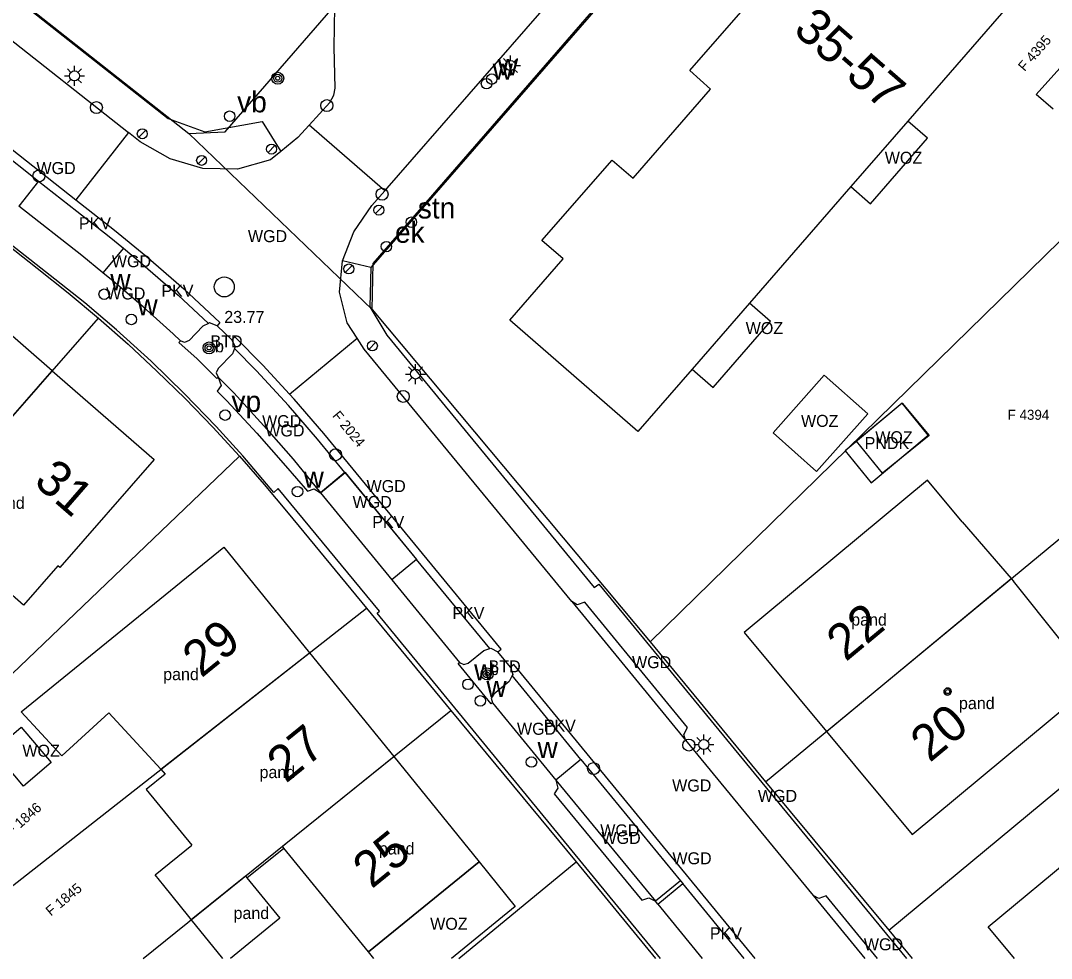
# Model space of a CAD drawing. Extents: x 198240 to 198429, y 356553 to 356721.
# Drawn here: x 198326.7 to 198378.2, y 356553.7 to 356600.6 of the extents above; entities that cross this region are included whole.
import ezdxf

# ---------------------------------------------------------------- set-up
doc = ezdxf.new("R2010")
doc.units = 0
for name, color, linetype in [('(presentatie) Code PNDK (symbool) (zonder attributen) niet in de presentatietabel', 7, 'Continuous'), ('Afsluitpaal', 7, 'Continuous'), ('begroeid terreindeel kenmerkpunt', 7, 'Continuous'), ('Benzineput_olieput', 7, 'Continuous'), ('bijgebouw', 7, 'Continuous'), ('BOOM', 7, 'Continuous'), ('Elektrakast', 7, 'Continuous'), ('grens individueel parkeervak', 7, 'Continuous'), ('Grens maaiveld', 7, 'Continuous'), ('grens WOZ object', 7, 'Continuous'), ('hoofdgebouw', 7, 'Continuous'), ('Hoogtepunt', 7, 'Continuous'), ('huisnummerreeks BGT', 7, 'Continuous'), ('identificerend kenmerkpunt bijpand', 7, 'Continuous'), ('identificerend kenmerkpunt pand', 7, 'Continuous'), ('identificerend kenmerkpunt parkeervak', 7, 'Continuous'), ('identificerend kenmerkpunt WOZ object', 7, 'Continuous'), ('Inspectieput_rioolput', 7, 'Continuous'), ('kant verharding', 7, 'Continuous'), ('kolk', 7, 'Continuous'), ('LICHTMAST', 7, 'Continuous'), ('Perceelnummer', 7, 'Continuous'), ('perceelsgrens_definitief', 7, 'Continuous'), ('straatnaambord', 7, 'Continuous'), ('tussenmuur', 7, 'Continuous'), ('Verkeersbordpaal', 7, 'Continuous'), ('vlakafsluiter', 7, 'Continuous'), ('waterleidingput', 7, 'Continuous'), ('wegdeel kenmerkpunt', 7, 'Continuous'), ('weginrichtingselement', 7, 'Continuous'), ('weginrichtingselement lijn', 7, 'Continuous'), ('WOZ object als punt', 7, 'Continuous')]:
    doc.layers.add(name, color=color, linetype=linetype)

msp = doc.modelspace()

# ---------------------------------------------------------------- linework, layer by layer
at = {"layer": 'Afsluitpaal'}
for p, q in [((198332.936, 356595.135), (198332.586, 356594.778)), ((198339.402, 356594.368), (198339.052, 356594.011)), ((198335.905, 356593.805), (198335.555, 356593.448)), ((198344.772, 356591.316), (198344.422, 356590.959)), ((198343.267, 356588.372), (198342.917, 356588.015)), ((198344.446, 356584.522), (198344.096, 356584.165))]:
    msp.add_line(p, q, dxfattribs=at)
for centre in [(198332.763, 356594.955), (198339.229, 356594.188), (198335.732, 356593.625), (198344.599, 356591.136), (198343.094, 356588.192), (198344.273, 356584.342)]:
    msp.add_circle(centre, 0.25, dxfattribs=at)
at = {"layer": 'Benzineput_olieput'}
msp.add_circle((198336.905, 356580.881), 0.263, dxfattribs=at)
msp.add_circle((198336.905, 356580.881), 0.263, dxfattribs=at)
at = {"layer": 'bijgebouw'}
for points in [[(198338.001, 356557.734), (198339.644, 356555.708), (198337.168, 356553.702)], [(198336.789, 356553.702), (198335.216, 356555.641)]]:
    msp.add_lwpolyline(points, dxfattribs=at)
at = {"layer": 'BOOM'}
for centre, radius in [((198339.538, 356597.733), 0.3), ((198339.538, 356597.733), 0.2), ((198339.538, 356597.733), 0.1), ((198336.101, 356584.239), 0.3), ((198336.101, 356584.239), 0.2), ((198336.101, 356584.239), 0.1), ((198350.016, 356567.934), 0.3), ((198350.016, 356567.934), 0.2), ((198350.016, 356567.934), 0.1)]:
    msp.add_circle(centre, radius, dxfattribs=at)
at = {"layer": 'Elektrakast'}
msp.add_circle((198344.975, 356589.31), 0.263, dxfattribs=at)
msp.add_circle((198344.975, 356589.31), 0.263, dxfattribs=at)
at = {"layer": 'grens individueel parkeervak'}
for p, q in [((198327.572, 356592.592), (198326.591, 356591.338)), ((198331.82, 356589.23), (198330.793, 356588.001)), ((198342.903, 356578.007), (198341.674, 356576.997)), ((198342.903, 356578.007), (198346.485, 356573.651)), ((198346.485, 356573.651), (198345.25, 356572.636)), ((198354.71, 356563.653), (198353.457, 356562.625)), ((198358.553, 356556.415), (198359.805, 356557.441))]:
    msp.add_line(p, q, dxfattribs=at)
at = {"layer": 'Grens maaiveld'}
for p, q in [((198332.081, 356595.014), (198329.434, 356591.655)), ((198344.897, 356592.108), (198341.11, 356595.383)), ((198340.134, 356581.92), (198343.518, 356584.725)), ((198341.674, 356576.997), (198342.904, 356578.006)), ((198342.904, 356578.006), (198342.903, 356578.007)), ((198342.904, 356578.006), (198346.485, 356573.651)), ((198354.71, 356563.653), (198359.687, 356557.585)), ((198359.687, 356557.585), (198358.436, 356556.558)), ((198359.687, 356557.585), (198359.805, 356557.441))]:
    msp.add_line(p, q, dxfattribs=at)
for points in [[(198311.777, 356613.258), (198312.501, 356612.688), (198316.479, 356609.557), (198334.051, 356595.726), (198335.895, 356595.044), (198338.762, 356595.561)], [(198318.292, 356600.168), (198318.429, 356600.335), (198329.434, 356591.655)], [(198329.434, 356591.655), (198331.374, 356590.125), (198332.937, 356588.842), (198334.833, 356587.192), (198336.644, 356585.51), (198336.504, 356585.346)], [(198328.26, 356583.099), (198323.101, 356587.58), (198317.022, 356580.581)], [(198337.248, 356584.646), (198337.387, 356584.794), (198338.788, 356583.375), (198340.134, 356581.92)], [(198350.553, 356569.041), (198350.715, 356569.174), (198341.85, 356579.957), (198340.363, 356581.672), (198340.134, 356581.92)], [(198370.778, 356581.471), (198367.918, 356579.09), (198369.226, 356577.489), (198372.086, 356579.869), (198370.778, 356581.471)], [(198363.416, 356553.702), (198351.352, 356568.4), (198351.188, 356568.267)]]:
    msp.add_lwpolyline(points, dxfattribs=at)
at = {"layer": 'grens WOZ object'}
for p, q in [((198370.778, 356581.471), (198368.494, 356579.573)), ((198370.778, 356581.471), (198372.121, 356579.855)), ((198369.788, 356577.971), (198368.494, 356579.573)), ((198372.121, 356579.855), (198369.788, 356577.971)), ((198325.32, 356564.087), (198326.702, 356565.264)), ((198326.702, 356565.264), (198328.21, 356563.494)), ((198326.828, 356562.317), (198325.32, 356564.087)), ((198328.21, 356563.494), (198326.828, 356562.317)), ((198344.074, 356554.032), (198349.616, 356558.527)), ((198349.616, 356558.527), (198351.423, 356556.299)), ((198351.423, 356556.299), (198348.226, 356553.702)), ((198344.342, 356553.702), (198344.074, 356554.032))]:
    msp.add_line(p, q, dxfattribs=at)
for points in [[(198378.332, 356596.184), (198377.486, 356596.927), (198380.014, 356599.745), (198380.819, 356599.057)], [(198368.212, 356592.309), (198369.191, 356591.458), (198372.045, 356594.74), (198371.066, 356595.591)], [(198360.274, 356583.182), (198361.325, 356582.267), (198364.189, 356585.561), (198363.138, 356586.475)], [(198364.316, 356579.994), (198366.882, 356582.876), (198369.06, 356580.937), (198366.494, 356578.055), (198364.316, 356579.994)]]:
    msp.add_lwpolyline(points, dxfattribs=at)
at = {"layer": 'hoofdgebouw'}
for p, q in [((198376.42, 356601.748), (198371.066, 356595.591)), ((198371.066, 356595.591), (198368.212, 356592.309)), ((198368.212, 356592.309), (198363.138, 356586.475)), ((198363.138, 356586.475), (198360.274, 356583.182)), ((198373.784, 356575.541), (198376.235, 356572.701)), ((198376.235, 356572.701), (198376.341, 356572.579)), ((198378.73, 356569.587), (198376.341, 356572.579)), ((198341.127, 356568.99), (198345.342, 356563.794)), ((198338.001, 356557.734), (198339.848, 356559.221)), ((198335.084, 356555.804), (198333.833, 356557.347)), ((198335.216, 356555.641), (198335.084, 356555.804))]:
    msp.add_line(p, q, dxfattribs=at)
for points in [[(198360.274, 356583.182), (198357.56, 356580.061), (198351.153, 356585.634), (198353.818, 356588.702), (198352.758, 356589.611), (198356.269, 356593.637), (198357.324, 356592.737), (198361.192, 356597.186), (198360.148, 356598.119), (198363.635, 356602.123), (198364.703, 356601.223), (198369.86, 356607.147), (198368.781, 356608.057), (198372.281, 356612.093), (198373.369, 356611.185), (198377.239, 356615.604), (198376.168, 356616.531), (198379.668, 356620.576), (198380.75, 356619.653), (198383.405, 356622.721), (198387.106, 356619.502)], [(198328.26, 356583.099), (198333.365, 356578.665), (198328.634, 356573.26), (198328.544, 356573.339), (198326.816, 356571.37), (198323.857, 356573.967), (198321.738, 356571.528)], [(198373.784, 356575.541), (198372.046, 356577.633), (198362.87, 356570.009), (198366.989, 356565.052)], [(198328.73, 356563.83), (198326.698, 356566.044), (198336.841, 356574.272), (198341.127, 356568.99)], [(198366.989, 356565.052), (198371.275, 356559.894), (198380.45, 356567.516), (198378.73, 356569.587)], [(198328.73, 356563.83), (198331.088, 356565.993), (198333.686, 356563.16)], [(198345.342, 356563.794), (198349.616, 356558.527), (198344.074, 356554.032), (198339.848, 356559.221)], [(198333.686, 356563.16), (198333.902, 356562.925), (198332.951, 356562.145), (198335.236, 356559.358)], [(198376.395, 356553.702), (198375.087, 356555.277), (198384.259, 356562.891), (198385.996, 356560.798)], [(198333.833, 356557.347), (198333.406, 356557.874), (198335.236, 356559.358)]]:
    msp.add_lwpolyline(points, dxfattribs=at)
at = {"layer": 'Inspectieput_rioolput'}
msp.add_circle((198336.865, 356587.293), 0.5, dxfattribs=at)
at = {"layer": 'kant verharding'}
for p, q in [((198288.208, 356629.517), (198332.081, 356595.014)), ((198344.897, 356592.108), (198377.168, 356629.077)), ((198322.687, 356596.444), (198327.572, 356592.592)), ((198338.762, 356595.561), (198339.693, 356594.074)), ((198336.504, 356585.346), (198337.248, 356584.646)), ((198341.674, 356576.997), (198345.25, 356572.636)), ((198350.146, 356569.199), (198346.485, 356573.651)), ((198345.25, 356572.636), (198348.633, 356568.509)), ((198354.249, 356571.548), (198359.938, 356564.624)), ((198351.188, 356568.267), (198350.553, 356569.041)), ((198354.71, 356563.653), (198351.264, 356567.853)), ((198350.285, 356566.492), (198353.457, 356562.625)), ((198359.938, 356564.624), (198366.321, 356556.854)), ((198353.457, 356562.625), (198358.436, 356556.558)), ((198362.873, 356553.702), (198359.805, 356557.441)), ((198366.321, 356556.854), (198368.91, 356553.702)), ((198358.553, 356556.415), (198358.436, 356556.558)), ((198358.553, 356556.415), (198360.779, 356553.702))]:
    msp.add_line(p, q, dxfattribs=at)
for points in [[(198382.054, 356630.413), (198380.73, 356630.231), (198344.191, 356588.273)], [(198358.681, 356553.702), (198344.512, 356570.974), (198344.626, 356571.073), (198339.557, 356577.216), (198339.341, 356577.012), (198337.792, 356578.849), (198336.463, 356580.312), (198334.882, 356581.942), (198333.211, 356583.577), (198331.471, 356585.153), (198329.894, 356586.497), (198328.385, 356587.677), (198287.334, 356619.961)], [(198341.11, 356595.383), (198342.151, 356596.522), (198342.345, 356596.889), (198342.404, 356597.244), (198342.367, 356599.296), (198342.392, 356601.284), (198342.457, 356602.444)], [(198339.693, 356594.074), (198339.175, 356593.653), (198337.534, 356593.192), (198335.794, 356593.217), (198334.158, 356593.695), (198332.658, 356594.56), (198332.081, 356595.014)], [(198341.11, 356595.383), (198340.545, 356594.766), (198339.693, 356594.074)], [(198327.572, 356592.592), (198329.494, 356591.076), (198331.112, 356589.821), (198331.82, 356589.23)], [(198342.782, 356588.597), (198343.346, 356590.05), (198344.246, 356591.363), (198344.897, 356592.108)], [(198330.793, 356588.001), (198329.743, 356588.86), (198326.591, 356591.338)], [(198331.82, 356589.23), (198332.654, 356588.534), (198334.555, 356586.882), (198336.07, 356585.465)], [(198343.518, 356584.725), (198343.015, 356585.5), (198342.628, 356587.025), (198342.782, 356588.597)], [(198344.191, 356588.273), (198344.153, 356586.301), (198344.997, 356584.886), (198355.366, 356572.263), (198355.605, 356572.429), (198370.986, 356553.702)], [(198334.673, 356584.594), (198334.309, 356584.941), (198332.811, 356586.291), (198331.299, 356587.587), (198330.793, 356588.001)], [(198336.07, 356585.465), (198335.798, 356585.333), (198335.102, 356584.613), (198334.875, 356584.519), (198334.673, 356584.594)], [(198336.504, 356585.346), (198336.131, 356585.494), (198336.07, 356585.465)], [(198334.673, 356584.594), (198334.595, 356584.511), (198335.503, 356583.692), (198336.487, 356582.704), (198336.558, 356582.783)], [(198337.248, 356584.646), (198337.409, 356584.298), (198337.377, 356584.216)], [(198354.249, 356571.548), (198343.87, 356584.183), (198343.518, 356584.725)], [(198337.377, 356584.216), (198337.268, 356583.938), (198336.561, 356583.213), (198336.454, 356582.999), (198336.558, 356582.783)], [(198342.903, 356578.007), (198341.535, 356579.671), (198340.073, 356581.357), (198338.472, 356583.095), (198337.377, 356584.216)], [(198336.558, 356582.783), (198336.709, 356582.357), (198336.514, 356582.079), (198336.994, 356581.587), (198338.49, 356579.97), (198339.928, 356578.339), (198341.021, 356577.07), (198341.36, 356577.184), (198341.674, 356576.997)], [(198336.558, 356582.783), (198337.341, 356582.003), (198338.844, 356580.339), (198340.303, 356578.669), (198341.674, 356576.997)], [(198359.938, 356564.624), (198359.85, 356564.909), (198360.046, 356565.251), (198354.903, 356571.519), (198354.512, 356571.388), (198354.249, 356571.548)], [(198348.633, 356568.509), (198348.855, 356568.397), (198349.071, 356568.476), (198349.842, 356569.1), (198350.146, 356569.199)], [(198350.146, 356569.199), (198350.203, 356569.218), (198350.553, 356569.041)], [(198350.285, 356566.492), (198350.213, 356566.432), (198348.567, 356568.459), (198348.633, 356568.509)], [(198351.188, 356568.267), (198351.293, 356567.909), (198351.264, 356567.853)], [(198351.264, 356567.853), (198351.11, 356567.551), (198350.342, 356566.925), (198350.218, 356566.724), (198350.285, 356566.492)], [(198353.457, 356562.625), (198353.552, 356562.215), (198353.365, 356561.931), (198357.748, 356556.607), (198358.099, 356556.731), (198358.436, 356556.558)], [(198369.541, 356553.702), (198366.969, 356556.825), (198366.6, 356556.701), (198366.321, 356556.854)]]:
    msp.add_lwpolyline(points, dxfattribs=at)
at = {"layer": 'kolk'}
for centre in [(198330.468, 356596.267), (198341.996, 356596.364), (198327.59, 356592.846), (198344.757, 356591.932), (198345.818, 356581.813), (198342.433, 356578.901), (198360.106, 356564.374), (198355.338, 356563.198)]:
    msp.add_circle(centre, 0.3, dxfattribs=at)
at = {"layer": 'LICHTMAST'}
for p, q in [((198351.002, 356598.545), (198350.825, 356598.722)), ((198351.179, 356598.618), (198351.179, 356598.868)), ((198351.356, 356598.545), (198351.533, 356598.722)), ((198329.191, 356598.028), (198329.014, 356598.205)), ((198329.368, 356598.101), (198329.368, 356598.351)), ((198329.545, 356598.028), (198329.722, 356598.205)), ((198350.679, 356598.368), (198350.929, 356598.368)), ((198350.825, 356598.014), (198351.002, 356598.191)), ((198351.179, 356597.868), (198351.179, 356598.118)), ((198351.533, 356598.014), (198351.356, 356598.191)), ((198351.429, 356598.368), (198351.679, 356598.368)), ((198328.868, 356597.851), (198329.118, 356597.851)), ((198329.014, 356597.497), (198329.191, 356597.674)), ((198329.368, 356597.351), (198329.368, 356597.601)), ((198329.722, 356597.497), (198329.545, 356597.674)), ((198329.618, 356597.851), (198329.868, 356597.851)), ((198346.256, 356583.112), (198346.079, 356583.289)), ((198346.433, 356583.185), (198346.433, 356583.435)), ((198346.61, 356583.112), (198346.787, 356583.289)), ((198345.933, 356582.935), (198346.183, 356582.935)), ((198346.079, 356582.581), (198346.256, 356582.758)), ((198346.433, 356582.435), (198346.433, 356582.685)), ((198346.787, 356582.581), (198346.61, 356582.758)), ((198346.683, 356582.935), (198346.933, 356582.935)), ((198360.682, 356564.574), (198360.505, 356564.751)), ((198360.859, 356564.647), (198360.859, 356564.897)), ((198361.036, 356564.574), (198361.213, 356564.751)), ((198360.359, 356564.397), (198360.609, 356564.397)), ((198360.505, 356564.043), (198360.682, 356564.22)), ((198360.859, 356563.897), (198360.859, 356564.147)), ((198361.213, 356564.043), (198361.036, 356564.22)), ((198361.109, 356564.397), (198361.359, 356564.397))]:
    msp.add_line(p, q, dxfattribs=at)
for centre in [(198351.179, 356598.368), (198329.368, 356597.851), (198346.433, 356582.935), (198360.859, 356564.397)]:
    msp.add_circle(centre, 0.25, dxfattribs=at)
at = {"layer": 'perceelsgrens_definitief'}
for points in [[(198335.086, 356594.965), (198336.909, 356595.05), (198372.498, 356636.045)], [(198287.646, 356632.339), (198335.086, 356594.965)], [(198344.27, 356586.164), (198344.308, 356588.473), (198380.117, 356629.684), (198382.048, 356630.256)], [(198335.086, 356594.965), (198344.27, 356586.164)], [(198322.937, 356591.83), (198327.497, 356588.229)], [(198358.164, 356569.531), (198380.205, 356591.088)], [(198327.497, 356588.229), (198329.048, 356587.003), (198330.567, 356585.738)], [(198344.27, 356586.164), (198358.164, 356569.531)], [(198312.565, 356565.146), (198330.567, 356585.738)], [(198330.567, 356585.738), (198332.05, 356584.431), (198333.498, 356583.086), (198334.91, 356581.703), (198336.285, 356580.284), (198337.623, 356578.829)], [(198363.947, 356562.536), (198387.979, 356582.417)], [(198317.612, 356559.68), (198337.623, 356578.829)], [(198337.623, 356578.829), (198338.855, 356577.413), (198340.054, 356575.969)], [(198370.106, 356555.109), (198394.44, 356575.297), (198393.504, 356576.321)], [(198340.054, 356575.969), (198343.976, 356571.222)], [(198322.461, 356554.365), (198343.976, 356571.222)], [(198343.976, 356571.222), (198348.206, 356566.1)], [(198358.164, 356569.531), (198363.947, 356562.536)], [(198332.808, 356553.702), (198348.206, 356566.1)], [(198348.206, 356566.1), (198354.461, 356558.524)], [(198363.947, 356562.536), (198370.106, 356555.109)], [(198348.592, 356553.702), (198354.461, 356558.524)], [(198354.461, 356558.524), (198358.444, 356553.702)], [(198370.106, 356555.109), (198371.272, 356553.702)]]:
    msp.add_lwpolyline(points, dxfattribs=at)
at = {"layer": 'straatnaambord'}
msp.add_circle((198346.224, 356590.532), 0.263, dxfattribs=at)
msp.add_circle((198346.224, 356590.532), 0.263, dxfattribs=at)
at = {"layer": 'tussenmuur'}
for p, q in [((198322.202, 356576.169), (198328.26, 356583.099)), ((198366.989, 356565.052), (198376.235, 356572.701)), ((198333.686, 356563.16), (198341.127, 356568.99))]:
    msp.add_line(p, q, dxfattribs=at)
for points in [[(198339.848, 356559.221), (198339.774, 356559.311), (198345.342, 356563.794)], [(198335.216, 356555.641), (198337.928, 356557.824), (198338.001, 356557.734)]]:
    msp.add_lwpolyline(points, dxfattribs=at)
at = {"layer": 'Verkeersbordpaal'}
msp.add_circle((198337.134, 356595.834), 0.263, dxfattribs=at)
at = {"layer": 'vlakafsluiter'}
msp.add_line((198344.191, 356588.273), (198342.782, 356588.597), dxfattribs=at)
at = {"layer": 'waterleidingput'}
for centre in [(198349.987, 356597.462), (198349.987, 356597.462), (198350.244, 356597.688), (198350.244, 356597.688), (198330.859, 356586.928), (198330.859, 356586.928), (198332.215, 356585.667), (198332.215, 356585.667), (198340.528, 356577.054), (198340.528, 356577.054), (198349.058, 356567.411), (198349.058, 356567.411), (198349.672, 356566.582), (198349.672, 356566.582), (198352.232, 356563.523), (198352.232, 356563.523)]:
    msp.add_circle(centre, 0.263, dxfattribs=at)
at = {"layer": 'weginrichtingselement lijn'}
for points in [[(198318.292, 356600.168), (198318.429, 356600.335), (198329.434, 356591.655)], [(198329.434, 356591.655), (198331.374, 356590.125), (198332.937, 356588.842), (198334.833, 356587.192), (198336.644, 356585.51), (198336.504, 356585.346)], [(198337.248, 356584.646), (198337.387, 356584.794), (198338.788, 356583.375), (198340.134, 356581.92)], [(198350.553, 356569.041), (198350.715, 356569.174), (198341.85, 356579.957), (198340.363, 356581.672), (198340.134, 356581.92)], [(198363.416, 356553.702), (198351.352, 356568.4), (198351.188, 356568.267)]]:
    msp.add_lwpolyline(points, dxfattribs=at)
at = {"layer": 'WOZ object als punt'}
for radius in [0.178, 0.178, 0.178, 0.178, 0.1, 0.1, 0.1, 0.1]:
    msp.add_circle((198373.05, 356567.048), radius, dxfattribs=at)
for start, end in [(0, 180), (0, 180), (0, 180), (0, 180), (0, 180), (0, 180), (0, 180), (0, 180), (180, 0), (180, 0), (180, 0), (180, 0), (180, 0), (180, 0), (180, 0), (180, 0)]:
    msp.add_arc((198373.05, 356567.048), 0.178, start, end, dxfattribs=at)

# ---------------------------------------------------------------- texts
at = {"layer": '(presentatie) Code PNDK (symbool) (zonder attributen) niet in de presentatietabel'}
msp.add_text('PNDK', height=0.6, dxfattribs=at).set_placement((198368.901, 356579.18))
at = {"layer": 'begroeid terreindeel kenmerkpunt'}
for p in [(198336.176, 356584.27), (198350.088, 356568.01)]:
    msp.add_text('BTD', height=0.6, dxfattribs=at).set_placement(p)
at = {"layer": 'Benzineput_olieput'}
msp.add_text('vp', height=1.05, dxfattribs=at).set_placement((198337.225, 356581.042))
at = {"layer": 'Elektrakast'}
msp.add_text('ek', height=1.05, dxfattribs=at).set_placement((198345.404, 356589.501))
at = {"layer": 'Hoogtepunt'}
msp.add_text('23.77', height=0.6, dxfattribs=at).set_placement((198336.865, 356585.493))
msp.add_text('23.77', height=0.6, dxfattribs=at).set_placement((198336.865, 356585.493))
at = {"layer": 'huisnummerreeks BGT'}
for s, rotation, p in [('35-57', 319, (198365.268, 356600.059)), ('31', 319, (198327.272, 356577.467)), ('22', 39.7, (198367.956, 356568.513)), ('29', 39.1, (198335.718, 356567.7)), ('20', 39.7, (198372.155, 356563.468)), ('27', 39, (198339.946, 356562.431)), ('25', 39.1, (198344.24, 356557.15))]:
    msp.add_text(s, height=1.8, rotation=rotation, dxfattribs=at).set_placement(p)
at = {"layer": 'identificerend kenmerkpunt bijpand'}
msp.add_text('pand', height=0.6, dxfattribs=at).set_placement((198337.328, 356555.67))
at = {"layer": 'identificerend kenmerkpunt pand'}
for p in [(198325.098, 356576.19), (198368.228, 356570.35), (198333.808, 356567.62), (198373.618, 356566.17), (198338.628, 356562.72), (198344.598, 356558.9)]:
    msp.add_text('pand', height=0.6, dxfattribs=at).set_placement(p)
at = {"layer": 'identificerend kenmerkpunt parkeervak'}
for p in [(198329.595, 356590.182), (198333.718, 356586.8), (198344.265, 356575.239), (198348.277, 356570.685), (198352.846, 356565.049), (198361.157, 356554.654)]:
    msp.add_text('PKV', height=0.6, dxfattribs=at).set_placement(p)
at = {"layer": 'identificerend kenmerkpunt WOZ object'}
for p in [(198369.907, 356593.454), (198362.95, 356584.935), (198365.717, 356580.293), (198369.432, 356579.474), (198326.765, 356563.791), (198347.165, 356555.131)]:
    msp.add_text('WOZ', height=0.6, dxfattribs=at).set_placement(p)
at = {"layer": 'Perceelnummer'}
for s, rotation, p in [('F 4395', 49.1, (198376.907, 356598.041)), ('F 2024', 309.6, (198342.242, 356580.835)), ('F 1846', 41.4, (198326.208, 356559.795)), ('F 1845', 39.7, (198328.19, 356555.794))]:
    msp.add_text(s, height=0.5, rotation=rotation, dxfattribs=at).set_placement(p)
msp.add_text('F 4394', height=0.5, dxfattribs=at).set_placement((198376.055, 356580.647))
at = {"layer": 'straatnaambord'}
msp.add_text('stn', height=1.05, dxfattribs=at).set_placement((198346.548, 356590.717))
at = {"layer": 'Verkeersbordpaal'}
msp.add_text('vb', height=1.05, dxfattribs=at).set_placement((198337.51, 356596.024))
at = {"layer": 'waterleidingput'}
for p in [(198350.548, 356597.886), (198350.291, 356597.66), (198331.163, 356587.126), (198332.519, 356585.865), (198340.832, 356577.252), (198349.362, 356567.609), (198349.976, 356566.78), (198352.536, 356563.721)]:
    msp.add_text('w', height=1.05, dxfattribs=at).set_placement(p)
at = {"layer": 'wegdeel kenmerkpunt'}
for p in [(198327.468, 356592.94), (198338.047, 356589.533), (198331.24, 356588.28), (198330.956, 356586.667), (198338.757, 356580.277), (198338.916, 356579.814), (198343.982, 356577.03), (198343.285, 356576.235), (198357.264, 356568.221), (198351.507, 356564.889), (198359.27, 356562.053), (198363.56, 356561.532), (198355.672, 356559.806), (198355.734, 356559.426), (198359.284, 356558.409), (198368.86, 356554.106)]:
    msp.add_text('WGD', height=0.6, dxfattribs=at).set_placement(p)
at = {"layer": 'weginrichtingselement'}
for p in [(198336.403, 356584.021), (198350.154, 356567.875)]:
    msp.add_text('b', height=0.6, rotation=0.2905, dxfattribs=at).set_placement(p)

doc.saveas('drawing.dxf')
